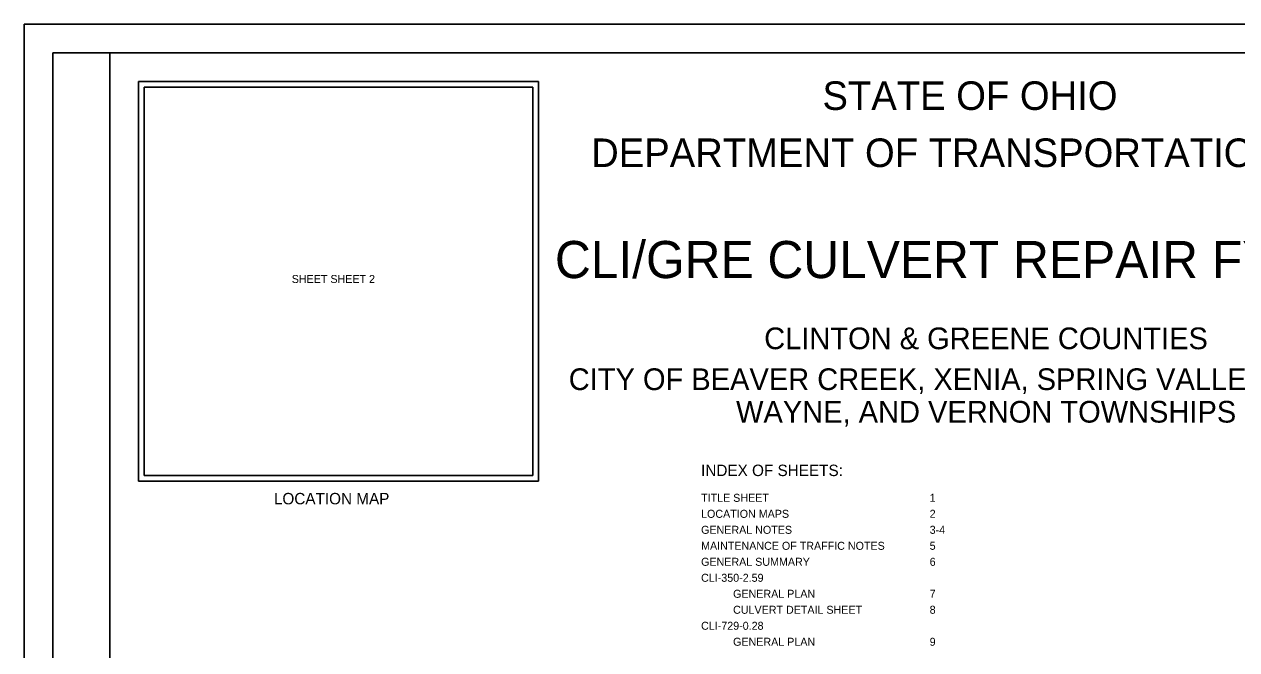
# Model space of a CAD drawing. Extents: x 43.1 to 77.1, y 2.7 to 24.7.
# Drawn here: x 43.13 to 64.35, y 13.71 to 24.66 of the extents above; entities that cross this region are included whole.
import ezdxf

# ---------------------------------------------------------------- set-up
doc = ezdxf.new("R2010")
doc.units = 0
for name, color, linetype in [('SH_Border', 7, 'Continuous'), ('SH_Cut_Line', 7, 'Continuous'), ('SH_Data', 7, 'Continuous'), ('SH_Text', 7, 'Continuous')]:
    doc.layers.add(name, color=color, linetype=linetype)

msp = doc.modelspace()

# ---------------------------------------------------------------- linework, layer by layer
at = {"layer": 'SH_Border'}
for points in [[(43.631, 24.158), (44.631, 24.158), (44.631, 3.158), (43.631, 3.158)], [(44.631, 24.158), (76.631, 24.158), (76.631, 3.158), (44.631, 3.158)]]:
    msp.add_lwpolyline(points, close=True, dxfattribs=at)
at = {"layer": 'SH_Cut_Line'}
msp.add_lwpolyline([(43.131, 2.658), (77.131, 2.658), (77.131, 24.658), (43.131, 24.658)], close=True, dxfattribs=at)
at = {"layer": 'SH_Data'}
for p, q in [((45.131, 23.658), (52.131, 23.658)), ((45.131, 23.658), (45.131, 16.658)), ((45.231, 23.558), (45.231, 16.758)), ((45.231, 23.558), (52.031, 23.558)), ((52.031, 23.558), (52.031, 16.758)), ((52.131, 23.658), (52.131, 16.658)), ((45.131, 16.658), (52.131, 16.658)), ((45.231, 16.758), (52.031, 16.758)), ((45.231, 16.758), (45.231, 16.758))]:
    msp.add_line(p, q, dxfattribs=at)

# ---------------------------------------------------------------- texts
at = {"layer": 'SH_Text'}
for s, height, p in [('STATE OF OHIO', 0.5, (57.099, 23.158)), ('DEPARTMENT OF TRANSPORTATION', 0.5, (53.051, 22.158)), ('CLI/GRE CULVERT REPAIR FY2024', 0.65, (52.417, 20.213)), ('SHEET SHEET 2', 0.14, (47.812, 20.128)), ('CLINTON & GREENE COUNTIES', 0.38, (56.079, 18.968)), ('CITY OF BEAVER CREEK, XENIA, SPRING VALLEY, GREEN,', 0.38, (52.659, 18.253)), ('WAYNE, AND VERNON TOWNSHIPS', 0.38, (55.587, 17.683)), ('INDEX OF SHEETS:', 0.2, (54.975, 16.747)), ('LOCATION MAP', 0.2, (47.5, 16.252)), ('TITLE SHEET', 0.14, (54.975, 16.296)), ('1', 0.14, (58.975, 16.296)), ('LOCATION MAPS', 0.14, (54.975, 16.016)), ('2', 0.14, (58.975, 16.016)), ('GENERAL NOTES', 0.14, (54.975, 15.736)), ('3-4', 0.14, (58.975, 15.736)), ('MAINTENANCE OF TRAFFIC NOTES', 0.14, (54.975, 15.456)), ('5', 0.14, (58.975, 15.456)), ('GENERAL SUMMARY', 0.14, (54.975, 15.176)), ('6', 0.14, (58.975, 15.176)), ('CLI-350-2.59', 0.14, (54.975, 14.896)), ('GENERAL PLAN', 0.14, (55.535, 14.616)), ('7', 0.14, (58.975, 14.616)), ('CULVERT DETAIL SHEET', 0.14, (55.535, 14.336)), ('8', 0.14, (58.975, 14.336)), ('CLI-729-0.28', 0.14, (54.975, 14.056)), ('GENERAL PLAN', 0.14, (55.535, 13.776)), ('9', 0.14, (58.975, 13.776))]:
    msp.add_text(s, height=height, dxfattribs=at).set_placement(p)

doc.saveas('drawing.dxf')
